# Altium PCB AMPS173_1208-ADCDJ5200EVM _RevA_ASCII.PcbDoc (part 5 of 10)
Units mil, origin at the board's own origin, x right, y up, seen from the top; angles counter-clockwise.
Board outline 10500 x 2750 mil, 14 copper layers (Top Copper, Layer 2 (GND1), Layer 3 (SIG1), Layer 4 (GND2, Layer 5 (PWR1), Layer 6 (GND3), Layer 7 (PWR/SIGNAL2), Layer 8 (PWR/SIGNAL3), Layer 9 (GND4), Layer 10 PWR2), Layer 11 (GND5), Layer 12 (SIG4), Layer 13 (GND6), Bottom Copper), stack 60.6 mil thick; 701 components, 826 nets, 3386 pads, 2128 vias.
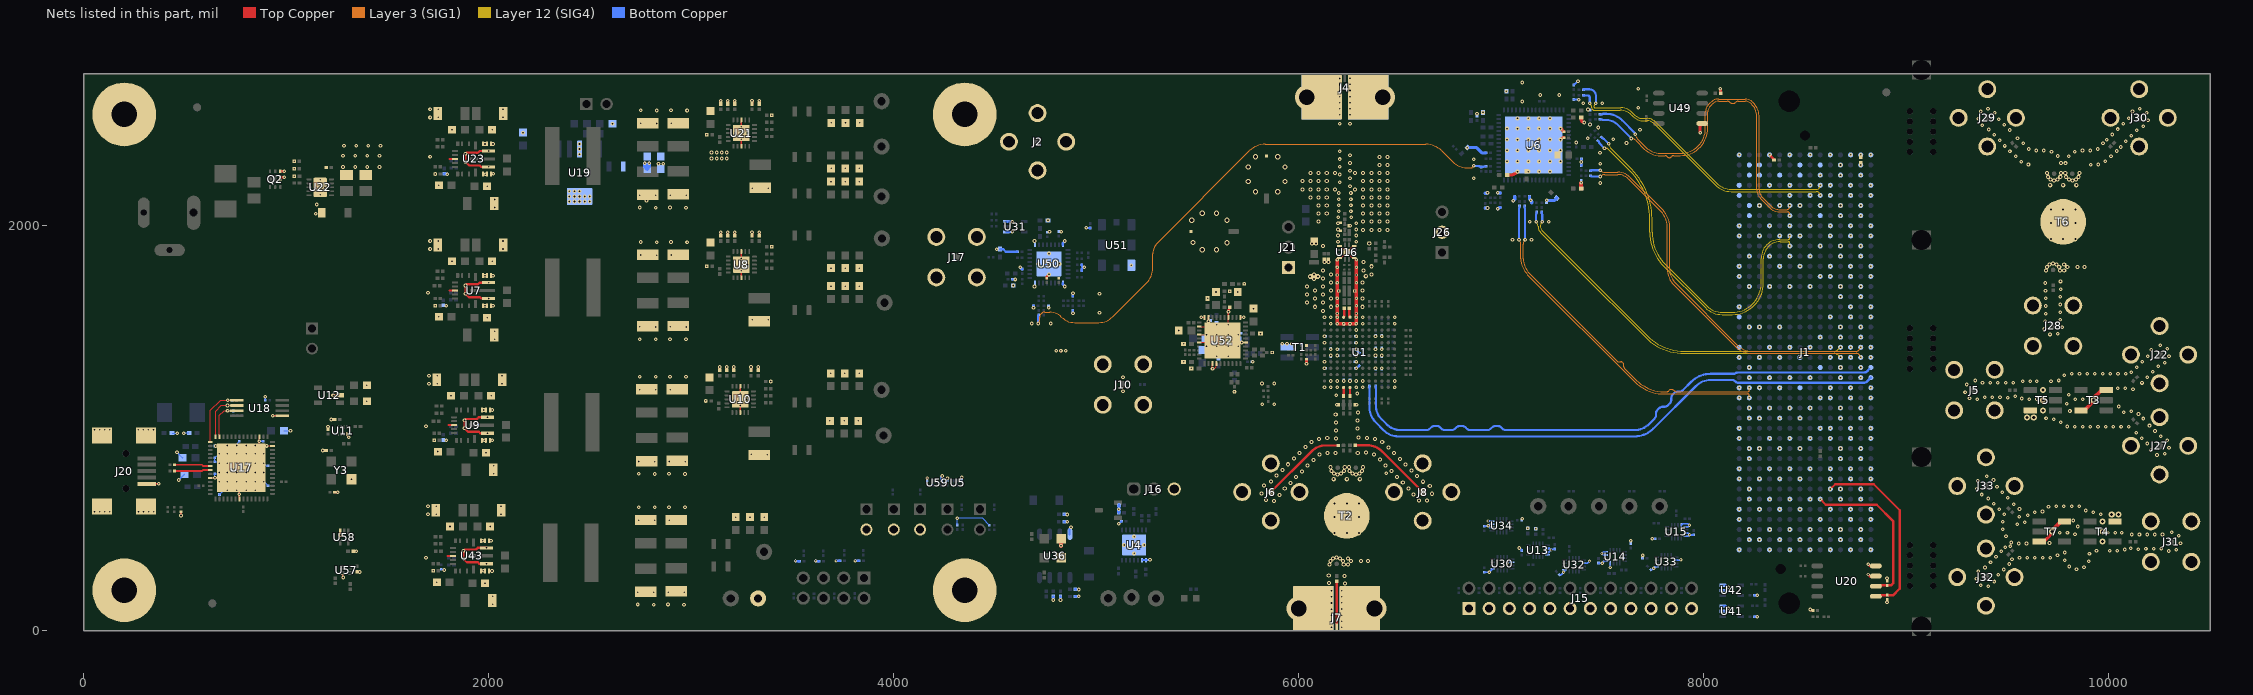
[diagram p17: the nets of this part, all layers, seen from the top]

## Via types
v1: diameter 18, hole 8, Top Copper to Bottom Copper, tented both sides, 1234 vias
v2: diameter 18, hole 8, Top Copper to Bottom Copper, tented top, 219 vias
v3: diameter 16, hole 8, Top Copper to Bottom Copper, tented both sides, 138 vias
v4: diameter 19.68, hole 7.87, Top Copper to Bottom Copper, 103 vias
v5: diameter 20, hole 10, Top Copper to Bottom Copper, tented top, 96 vias
v6: diameter 20, hole 10, Top Copper to Bottom Copper, tented both sides, 71 vias
v7: diameter 15.75/18/18/18/16/18/18/18/18/16/18/18/18/18 (per signal layer), hole 8, Top Copper to Bottom Copper, 50 vias
v8: diameter 20, hole 10, Top Copper to Bottom Copper, 40 vias
v9: diameter 15.75, hole 7.87, Top Copper to Bottom Copper, 28 vias
v10: diameter 21.81, hole 10, Top Copper to Bottom Copper, 26 vias
v11: diameter 15.75/16/16/16/16/16/16/16/16/16/16/16/16/18 (per signal layer), hole 8, Top Copper to Bottom Copper, 26 vias
v12: diameter 18, hole 8, Top Copper to Bottom Copper, tented bottom, 18 vias
v13: diameter 25.75, hole 15.75, Top Copper to Bottom Copper, 16 vias
v14: diameter 15.75/16/16/16/16/16/16/18/16/16/16/16/16/18 (per signal layer), hole 8, Top Copper to Bottom Copper, 15 vias
v15: diameter 30, hole 15, Top Copper to Bottom Copper, tented both sides, 12 vias
v16: diameter 15.75/16/16/16/18/16/16/16/16/16/16/16/16/18 (per signal layer), hole 8, Top Copper to Bottom Copper, 11 vias
v17: diameter 15.75/16/16/16/16/16/16/16/16/18/16/16/16/18 (per signal layer), hole 8, Top Copper to Bottom Copper, 7 vias
v18: diameter 15.75/16/16/16/16/16/16/18/16/18/16/16/16/18 (per signal layer), hole 8, Top Copper to Bottom Copper, 5 vias
v19: diameter 119.29, hole 77.95, Top Copper to Bottom Copper, 4 vias
v20: diameter 18, hole 8, Top Copper to Bottom Copper, 4 vias
v21: diameter 15.75/16/16/16/18/16/16/18/16/16/16/16/16/18 (per signal layer), hole 8, Top Copper to Bottom Copper, 2 vias
v22: diameter 15.75/16/16/16/16/16/18/16/16/16/16/16/16/18 (per signal layer), hole 8, Top Copper to Bottom Copper, 2 vias
v23: diameter 15.75/16/16/16/16/16/18/18/16/16/16/16/16/18 (per signal layer), hole 8, Top Copper to Bottom Copper, 1 vias

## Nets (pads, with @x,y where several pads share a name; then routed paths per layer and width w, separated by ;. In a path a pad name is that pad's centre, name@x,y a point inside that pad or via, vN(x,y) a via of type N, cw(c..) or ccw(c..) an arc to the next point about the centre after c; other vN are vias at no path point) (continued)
DB7_FMC_N: C44.1 J1.Y22 | length 2774.6
  Bottom Copper w10.5: C44.1@6381.14,1208.98 ccw(c6382.69,1207.43) 6381,1208.82 ccw(c6382.69,1207.43) 6380.5,1207.43 6380.5,1113.13 ccw(c6477.94,1113.13) 6409.04,1044.23 6433.65,1019.62 ccw(c6502.74,1088.71) 6502.74,991 6630,991 ; 7895.96,1186.96 7939.63,1230.63 cw(c8032.26,1138) 8032.26,1269 8148.99,1269 ccw(c8148.99,1279.69) 8156.55,1272.13 ; 7896,1187 cw(c7882.34,1200.66) 7882.34,1181.34 7873.36,1181.34 ccw(c7873.37,1154.03) 7854.06,1173.34 7845.8,1165.08 ccw(c7861.16,1149.72) 7839.43,1149.72 7839.43,1140.43 cw(c7815.29,1140.43) 7832.36,1123.36 7821,1112 cw(c7807.34,1125.66) 7807.34,1106.34 7798.36,1106.34 ccw(c7798.37,1079.03) 7779.06,1098.34 7770.8,1090.08 ccw(c7786.16,1074.72) 7764.43,1074.72 7764.43,1065.43 cw(c7740.29,1065.43) 7757.4,1048.4 cw(c7740.29,1065.43) 7757.36,1048.36 7729.29,1020.29 cw(c7658.58,1091) 7658.58,991 7021,991 ; 6630,991 ccw(c6630,1015.14) 6630.07,991 ; 6630,991 6630.07,991 ; 6630.07,991 ccw(c6630,1015.14) 6647.07,998.07 6653.64,1004.64 cw(c6669,989.27) 6669,1011 6680.69,1011 cw(c6680.69,983.69) 6699.99,1003.01 6706.34,996.66 ccw(c6720,1010.31) 6720,991 6755,991 ccw(c6755,1015.14) 6772.07,998.07 6778.64,1004.64 cw(c6794,989.27) 6794,1011 6805.69,1011 cw(c6805.69,983.69) 6824.99,1003.01 6831.34,996.66 ccw(c6845,1010.31) 6845,991 6931,991 ccw(c6931,1015.14) 6948.07,998.07 6954.64,1004.64 cw(c6970,989.27) 6970,1011 6981.69,1011 cw(c6981.69,983.69) 7000.99,1003.01 7007.34,996.66 ccw(c7021,1010.31) 7020.94,991 ; 7020.94,991 ccw(c7021,1010.31) 7021,991 ; 7020.94,991 7021,991
  Bottom Copper w11.5: 8156.55,1272.13 cw(c8167.9,1251.1) 8167.9,1275 8791.46,1275 ccw(c8791.46,1295.57) 8805.99,1281.01 J1.Y22@8817.32,1292.33
DB7_FMC_P: C43.1 J1.Y23 | length 2775.5
  Bottom Copper w10.5: C43.1@6348.85,1208.98 cw(c6347.28,1207.41) 6349,1208.81 cw(c6347.28,1207.41) 6349.5,1207.41 6349.5,1100.29 ccw(c6446.94,1100.29) 6378.04,1031.39 6420.14,989.29 ccw(c6490.85,1060) 6490.85,960 7658.58,960 ccw(c7658.58,1091) 7751.21,998.37 7961.55,1208.71 cw(c8032.26,1138) 8032.26,1238 8142,1238 cw(c8142,1223.17) 8152.48,1233.66 8152.96,1233.18
  Bottom Copper w11.5: 8152.96,1233.18 ccw(c8172.72,1252.94) 8172.72,1225 8788.45,1225 ccw(c8788.45,1252.9) 8808.17,1233.17 J1.Y23@8825,1250
EECLK: R168.1 U17.56 U18.2 | length 267.8
  Top Copper w5: U17.56@650.41,958.04 650.41,1083.41 679.59,1112.59 v1(709.41,1112.59) U18.2@756,1112.59
  Bottom Copper w5: v1(709.41,1112.59) 709.82,1113 R168.1@733.98,1113
EECS: R167.1 U17.1 U18.1 | length 330.2
  Top Copper w5: U17.1@624.82,932.45 624.82,1087.82 675.18,1138.18 v1(710.18,1138.18) U18.1@756,1138.18
  Bottom Copper w5: v1(710.18,1138.18) R167.1@732.98,1138.18
EEDATA: R170.2 U17.55 U18.3 | length 228.3
  Top Copper w5: U17.55@670.09,958.04 670.09,1063.09 694,1087 v1(710,1087) U18.3@756,1087
  Bottom Copper w5: v1(710,1087) 710.98,1086.02 R170.2@737,1086.02
FE_VDD: C113.1 C114.1 FB1.1 FB4.2
  other v1: 3100,2331.93 3125,2331.93 3150,2331.93 3175,2331.93 3100,2361.93 3125,2361.93 3150,2361.93 3175,2361.93
  other v5: 6076,1737 6056,1749 6096,1749 6076,1759
FGPA_GBTCLK5_FMC_N: J1.Z21 R44.2 | length 1871.4
  Layer 3 (SIG1) w3.25: v1(7489.42,2243.46) cw(c7512.06,2220.82) 7512.06,2252.83 7576,2252.83 cw(c7576,2180) 7627.5,2231.5 7790.71,2068.29 cw(c7720,1997.58) 7820,1997.58 7820,1786.17 ccw(c7931.25,1786.17) 7852.58,1707.51 8157.76,1402.33 ccw(c8236.42,1481) 8236.42,1369.75 8752.87,1369.75 cw(c8752.87,1350.12) 8766.73,1364.02 8770.93,1359.82 cw(c8761.12,1350) v2(8775,1350)
  Bottom Copper w10.5: R44.2@7441.02,2246.02 ccw(c7448.27,2253.27) 7448.27,2243.02 7488.38,2243.02 ccw(c7488.38,2244.5) v1(7489.42,2243.46)
FGPA_GBTCLK5_FMC_P: J1.Z20 R42.2 | length 1871
  Layer 3 (SIG1) w3.25: v1(7489.42,2273.46) ccw(c7512.06,2296.09) 7512.06,2264.08 7576,2264.08 cw(c7576,2180) 7635.46,2239.45 7798.67,2076.24 cw(c7720,1997.58) 7831.25,1997.58 7831.25,1786.17 ccw(c7931.25,1786.17) 7860.54,1715.46 8165.71,1410.29 ccw(c8236.42,1481) 8236.42,1381 8755,1381 ccw(c8755,1395.49) 8765.23,1385.23 8771.46,1391.46 ccw(c8762.93,1400) v2(8775,1400)
  Bottom Copper w10.5: R42.2@7441.02,2271.02 cw(c7448.27,2263.78) 7448.27,2274.02 7456.36,2274.02 7488.06,2274.02 cw(c7488.06,2272.09) v1(7489.42,2273.46)
FPGA_CLKA_FMC_N: J1.L25 R63.2 | length 1698.6
  Layer 3 (SIG1) w3.25: v1(7087.43,1931.41) cw(c7064.8,1908.78) 7096.81,1908.78 7096.81,1837.36 ccw(c7208.06,1837.36) 7129.39,1758.7 7658.95,1229.14 ccw(c7802.95,1373.13) 7802.95,1169.49 8217.66,1169.49 cw(c8217.66,1162.29) 8222.75,1167.38 cw(c8217.32,1161.95) 8225,1161.95 v2(8225,1150)
  Bottom Copper w10.5: v1(7087.43,1931.41) cw(c7088.48,1932.46) 7087,1932.46 7087,2082.62 cw(c7097.24,2082.62) 7090,2089.86 R63.2@7090,2097.95
FPGA_CLKA_FMC_P: J1.L24 R62.2 | length 1696.3
  Layer 3 (SIG1) w3.25: v1(7117.43,1931.41) ccw(c7140.07,1908.78) 7108.06,1908.78 7108.06,1837.36 ccw(c7208.06,1837.36) 7137.35,1766.65 7572.08,1331.92 ccw(c7581.62,1341.46) 7581.62,1327.97 7590.34,1327.97 cw(c7590.34,1315.75) 7598.98,1324.39 7603.42,1319.95 cw(c7598.06,1314.6) 7605.63,1314.6 7605.63,1303.01 ccw(c7616.83,1303.01) 7608.9,1295.1 7666.91,1237.09 ccw(c7802.95,1373.13) 7802.95,1180.74 7818.23,1180.74 ccw(c7818.23,1191.61) 7825.91,1183.92 7828.6,1186.61 cw(c7839.17,1176.05) 7839.17,1190.99 7840.42,1190.99 cw(c7840.42,1170.13) 7855.17,1184.88 7856,1184.06 ccw(c7864,1192.06) 7864,1180.74 8217.73,1180.74 ccw(c8217.73,1188.29) 8223.07,1182.95 ccw(c8218.41,1187.61) 8225,1187.61 v2(8225,1200)
  Bottom Copper w10.5: R62.2@7115,2097.95 7115,2089.86 cw(c7107.76,2082.62) 7118,2082.62 7118,1932.78 cw(c7116.06,1932.78) v1(7117.43,1931.41)
FPGA_CLKB_FMC_N: J1.G7 R40.2 | length 1676.1
  Layer 3 (SIG1) w3.25: v1(7641.16,2431.16) cw(c7641.16,2399.15) 7663.79,2421.78 7706.53,2379.04 ccw(c7785.2,2457.71) 7785.2,2346.46 7810,2346.46 cw(c7810,2335.5) 7817.75,2343.25 7821.88,2339.12 ccw(c7827,2344.24) 7827,2337 7832,2337 ccw(c7832,2346.66) 7838.83,2339.83 7840.84,2341.84 cw(c7852,2330.67) 7852,2346.46 7884.68,2346.46 ccw(c7884.68,2481.47) 8019.69,2481.47 8019.69,2563.24 cw(c8058,2563.24) 8030.91,2590.33 8041,2600.42 cw(c8075.06,2566.36) 8075.06,2614.53 8117,2614.53 cw(c8117,2598.91) 8128.05,2609.96 ccw(c8140,2621.9) 8140,2605 8148,2605 ccw(c8148,2617.07) 8156.54,2608.54 8157.96,2609.96 cw(c8169,2598.91) 8169,2614.53 8206,2614.53 cw(c8206,2579.5) 8230.77,2604.27 8240.39,2594.65 cw(c8188.32,2542.59) 8261.95,2542.59 8261.95,2179.22 ccw(c8326.8,2179.22) 8280.95,2133.37 8327.45,2086.86 ccw(c8371.16,2130.56) 8364.54,2069.11 ccw(c8371.16,2130.56) 8371.16,2068.75 8413.81,2068.75 cw(c8413.81,2057.56) 8425,2057.56 v2(8425,2050)
  Bottom Copper w10.5: R40.2@7487.05,2525 7495.14,2525 cw(c7495.14,2514.76) 7502.38,2522 7520,2522 cw(c7520,2444.75) 7574.63,2499.37 v1@7639.97,2434.03 ; v1@7639.98,2434.02 cw(c7637.1,2431.16) v1(7641.16,2431.16)
FPGA_CLKB_FMC_P: J1.G6 R37.2 | length 1680.2
  Layer 3 (SIG1) w3.25: v1(7662.37,2452.37) ccw(c7694.38,2452.37) 7671.75,2429.74 7714.49,2387 ccw(c7785.2,2457.71) 7785.2,2357.71 7884.68,2357.71 ccw(c7884.68,2481.47) 8008.44,2481.47 8008.44,2563.24 cw(c8058,2563.24) 8022.96,2598.29 8033.05,2608.38 ; 8033.05,2608.37 cw(c8075.06,2566.36) 8075.06,2625.78 8206,2625.78 cw(c8206,2579.5) 8238.72,2612.22 8248.34,2602.61 cw(c8188.32,2542.59) 8273.2,2542.59 8273.2,2179.22 ccw(c8326.8,2179.22) 8288.9,2141.32 8335.41,2094.81 ccw(c8371.16,2130.56) 8354.03,2082.99 ccw(c8371.16,2130.56) 8371.16,2080 8410,2080 ccw(c8410,2095) 8425,2095 v2(8425,2100)
  Bottom Copper w10.5: R37.2@7487.05,2550 7495.14,2550 ccw(c7495.14,2560.24) 7502.38,2553 7520,2553 cw(c7520,2444.75) 7596.55,2521.29 7660.18,2457.66 cw(c7654.9,2452.37) v1(7662.37,2452.37)
FPGA_GBTCLK0_FMC_N: J1.D5 R227.2 | length 1385.7
  Layer 12 (SIG4) w3.25: v1@7441.2,2600.45 cw(c7428.74,2588) 7446.35,2588 7446.35,2583.34 ccw(c7458.81,2583.34) 7458.81,2570.88 7586.41,2570.88 cw(c7586.41,2491.91) 7642.25,2547.75 7652.05,2537.95 ccw(c7698.41,2584.32) 7698.41,2518.75 7720,2518.75 cw(c7720,2472.06) 7753,2505.09 ; 7753.02,2505.07 7980.05,2278.05 8056.76,2201.33 ccw(c8135.42,2280) 8135.42,2168.75 8556.25,2168.75 cw(c8556.25,2150) v2(8575,2150)
  Bottom Copper w10.5: R227.2@7405.21,2644.98 ccw(c7407.21,2644.98) 7407.21,2642.98 7427.64,2642.98 cw(c7427.64,2633.86) 7436.76,2633.86 7436.76,2604.89 v1(7436.98,2604.67)
FPGA_GBTCLK0_FMC_P: J1.D4 R226.2 | length 1419
  Layer 12 (SIG4) w3.25: v1@7462.76,2600.45 ccw(c7475.22,2588) 7457.61,2588 ccw(c7463.48,2588) 7463.48,2582.13 7591.07,2582.13 cw(c7591.07,2503.16) 7646.89,2559.02 7660,2545.91 ; 7660.03,2545.88 ccw(c7698.41,2584.32) 7698.41,2530 7720,2530 cw(c7720,2472.06) 7760.97,2513.03 7988,2286 8064.71,2209.29 ccw(c8135.42,2280) 8135.42,2180 8555,2180 ccw(c8555,2200) v2(8575,2200)
  Bottom Copper w10.5: R226.2@7405.21,2671.98 cw(c7407.21,2671.98) 7407.21,2673.98 7435.53,2673.98 cw(c7435.53,2642.98) 7457.45,2664.9 cw(c7432.56,2640.01) 7467.76,2640.01 7467.76,2606.55 cw(c7465.1,2606.55) v1(7466.98,2604.67)
FPGA_GBTCLK1_FMC_N: J1.B21 R41.2 | length 1831.4
  Layer 12 (SIG4) w3.25: v1(7172.03,2019.51) 7172.82,2018.72 cw(c7152.11,1998) 7181.4,1998 ccw(c7225.61,1998) 7194.34,1966.75 7369.91,1791.18 7712.33,1448.76 ccw(c7903.08,1639.51) 7903.08,1369.75 8643.34,1369.75 cw(c8643.34,1341) 8663.67,1361.33 v2(8675,1350)
  Bottom Copper w10.5: v1(7172.03,2019.51) cw(c7173.07,2020.56) 7171.59,2020.56 7171.59,2052.57 cw(c7181.84,2052.57) 7174.59,2059.82 R41.2@7174.59,2067.91
FPGA_GBTCLK1_FMC_P: J1.B20 R38.2 | length 1813.9
  Layer 12 (SIG4) w3.25: v1(7202.03,2019.51) 7201.23,2018.72 ccw(c7221.95,1998) 7192.65,1998 ccw(c7225.61,1998) 7202.31,1974.69 7720.29,1456.71 ccw(c7903.08,1639.5) 7903.08,1381 8648,1381 ccw(c8648,1400.31) 8661.66,1386.66 v2(8675,1400)
  Bottom Copper w10.5: R38.2@7199.59,2067.91 7199.59,2059.82 cw(c7192.35,2052.57) 7202.59,2052.57 7202.59,2020.88 cw(c7200.66,2020.88) v1(7202.03,2019.51)
FPGA_SYSREF_FMC_N: J1.G10 R53.2 | length 1726.2
  Layer 12 (SIG4) w3.25: v1(7509.84,2383) 7519.7,2383 cw(c7519.7,2374.81) 7525.49,2380.6 7635.36,2270.74 cw(c7398.5,2033.88) 7733.47,2033.88 7733.47,1967.2 ccw(c7968.23,1967.2) 7802.23,1801.2 8006.72,1596.71 ccw(c8091.79,1681.78) 8091.79,1561.47 8141.2,1561.47 ccw(c8141.2,1714.65) 8294.38,1714.65 8294.38,1838.21 cw(c8376.92,1838.21) 8376.92,1920.75 8417.51,1920.75 cw(c8417.51,1913.26) 8425,1913.26 v2@8425,1901.5
  Bottom Copper w10.5: R53.2@7477.43,2419.04 7483.15,2413.32 ccw(c7493.39,2413.32) 7486.15,2406.08 7508.79,2383.44 ccw(c7509.84,2384.48) v1(7509.84,2383)
  other v2: 8425,1900
FPGA_SYSREF_FMC_P: J1.G9 R51.2 | length 1715.1
  Layer 12 (SIG4) w3.25: v1(7531.05,2404.22) ccw(c7563.06,2404.22) 7540.42,2381.58 7643.32,2278.69 cw(c7398.51,2033.88) 7744.72,2033.88 7744.72,1967.2 ccw(c7968.22,1967.2) 7810.18,1809.16 8014.68,1604.66 ccw(c8091.79,1681.78) 8091.79,1572.72 8141.2,1572.72 ccw(c8141.2,1714.65) 8283.13,1714.65 8283.13,1840.04 cw(c8375.09,1840.04) 8375.09,1932 8415.67,1932 ccw(c8415.67,1941.33) 8425,1941.33 v2(8425,1950)
  Bottom Copper w10.5: R51.2@7495.1,2436.72 7500.83,2431 cw(c7500.83,2420.75) 7508.06,2428 7530.48,2405.59 cw(c7529.11,2404.22) v1(7531.05,2404.22)
FTDI_D_N: R156.2 U17.7 | length 180.1
  Top Copper w9.5: R156.2@447.05,820 583.5,820 589.16,814.34 U17.7@624.82,814.34
FTDI_D_P: R157.2 U17.8 | length 180.1
  Top Copper w9.5: 583.5,789 589.16,794.66 U17.8@624.82,794.66
  Top Copper w10: R157.2@447.02,789 583.5,789
GA0_FMC: J1.C34 R218.1 U20.1 | length 927.4
  Top Copper w11.5: v2(8625,700) 8649,724 8839,724 8968,595 8968,208 8934.81,174.81 8854.5,174.81 U20.1@8849.68,170
GA1_FMC: J1.D35 R220.1 U20.2 | length 803.3
  Top Copper w11.5: v2(8575,650) 8602.25,622.75 8854.25,622.75 8935,542 8935,235 8923.98,223.98 R220.1@8905,223.98 8853.66,223.98 U20.2@8849.68,220
GND: C6.2 C7.2 C8.2 C9.2 C10.2 C11.2 C12.2 C47.2 C48.2 C51.2 C53.1 C54.1 C55.1 C56.1 C57.1 C58.2 C59.2 C62.2 C63.2 C64.2 C65.2 C66.2 C68.2 C69.2 C70.2 C71.2 C72.2 C76.1 C77.1 C78.1 C79.1 C80.2 C81.1 C82.1 C83.2 C84.1 C85.2 C86.1 C87.2 C88.2 C89.1 C92.2 C94.2 C95.2 C96.2 C97.2 C100.2 C101.2 C102.2 C103.2 C104.2 C106.1 C109.2 C110.2 C111.2 C112.2 C113.2 C114.2 C115.1 C116.1 C118.1 C124.1 C125.1 C126.2 C128.2 C130.2 C131.2 C132.2 C133.2 C134.2 C135.2 C136.1 C137.1 C139.2 C140.2 C141.2 C142.2 C144.2 C145.2 C146.2 C147.2 C156.1 C157.1 C158.1 C159.1 C160.1 C161.1 C162.1 C163.1 C167.1 C168.1 C169.1 C170.1 C171.1 C172.1 C173.1 C174.1 C175.1 C176.1 C178.1 C179.1 C180.1 C181.1 C182.1 C183.1 C184.2 C185.2 C186.2 C187.2 C188.2 C189.2 C190.2 C192.1 C193.1 C195.2 C199.2 C201.2 C202.2 C203.2 C204.1 C205.2 C206.2 C207.1 C209.2 C210.2 C211.2 C212.2 C213.2 C214.2 C215.2 C216.2 C217.2 C218.2 C220.1 C221.1 C223.2 C224.2 C225.2 C226.2 C227.2 C229.2 C230.2 C231.2 C236.2 C237.2 C241.2 C242.2 C243.2 C244.2 C245.2 C287.1 C288.1 C290.2 C307.2 C308.2 C309.2 C310.2 C311.2 C312.2 C313.2 C314.2 C315.2 C316.2 C317.2 C318.2 C320.2 C323.2 C324.2 C325.2 C326.2 C327.1 C328.1 C329.1 C330.1 C331.2 C332.2 C333.2 C334.2 C335.2 C336.2 C338.2 C339.1 C340.1 C341.1 C342.1 C343.1 C344.1 C345.1 C359.1 C360.1 C405.1 C415.2 C416.2 C417.2 C421.2 C422.2 C423.2 C424.2 C425.2 C426.2 C427.2 C428.2 C429.2 C430.2 C431.2 C432.2 C433.2 D2.2 D3.2 D6.2 H1.1 H2.1 H3.1 H4.1 J1.A1 J1.A4 J1.A5 J1.A8 J1.A9 J1.A12 J1.A13 J1.A16 J1.A17 J1.A20 J1.A21 J1.A24 J1.A25 J1.A28 J1.A29 J1.A32 J1.A33 J1.A36 J1.A37 J1.A40 J1.B2 J1.B3 J1.B6 J1.B7 J1.B10 J1.B11 J1.B14 J1.B15 J1.B18 J1.B19 J1.B22 J1.B23 J1.B26 J1.B27 J1.B30 J1.B31 J1.B34 J1.B35 J1.B38 J1.B39 J1.C1 J1.C4 J1.C5 J1.C8 J1.C9 J1.C12 J1.C13 J1.C17 J1.C20 J1.C21 J1.C24 J1.C25 J1.C28 J1.C29 J1.C32 J1.C33 J1.C36 J1.C38 J1.C40 J1.D2 J1.D3 J1.D6 J1.D7 J1.D10 J1.D13 J1.D19 J1.D22 J1.D25 J1.D28 J1.D37 J1.D39 J1.E1 J1.E4 J1.E5 J1.E8 J1.E11 J1.E14 J1.E20 J1.E23 J1.E26 J1.E29 J1.E32 J1.E35 J1.E38 J1.E40 J1.F2 J1.F3 J1.F6 J1.F9 J1.F12 J1.F21 J1.F24 J1.F27 J1.F30 J1.F33 J1.F36 J1.F39 J1.G1 J1.G4 J1.G5 J1.G8 J1.G11 J1.G14 J1.G20 J1.G23 J1.G26 J1.G29 J1.G32 J1.G35 J1.G38 J1.G40 J1.H3 J1.H6 J1.H9 J1.H12 J1.H18 J1.H21 J1.H24 J1.H27 J1.H30 J1.H33 J1.H36 J1.H39 J1.J1 J1.J4 J1.J8 J1.J11 J1.J14 J1.J20 J1.J23 J1.J26 J1.J29 J1.J32 J1.J35 J1.J38 J1.J40 J1.K2 J1.K3 J1.K6 J1.K9 J1.K18 J1.K21 J1.K24 J1.K27 J1.K30 J1.K33 J1.K36 J1.K39 J1.L2 J1.L3 J1.L6 J1.L7 J1.L11 J1.L14 J1.L18 J1.L22 J1.L23 J1.L26 J1.L27 J1.L30 J1.L31 J1.L34 J1.L35 J1.L38 J1.L39 J1.M1 J1.M4 J1.M5 J1.M8 J1.M9 J1.M12 J1.M13 J1.M16 J1.M17 J1.M20 J1.M21 J1.M24 J1.M25 J1.M28 J1.M29 J1.M32 J1.M33 J1.M36 J1.M37 J1.M40 J1.Y1 J1.Y4 J1.Y5 J1.Y8 J1.Y9 J1.Y12 J1.Y13 J1.Y16 J1.Y17 J1.Y20 J1.Y21 J1.Y24 J1.Y25 J1.Y28 J1.Y29 J1.Y32 J1.Y33 J1.Y36 J1.Y37 J1.Y40 J1.Z2 J1.Z3 J1.Z6 J1.Z7 J1.Z10 J1.Z11 J1.Z14 J1.Z15 J1.Z18 J1.Z19 J1.Z22 J1.Z23 J1.Z26 J1.Z27 J1.Z30 J1.Z31 J1.Z34 J1.Z35 J1.Z38 J1.Z39 J2.2 J2.3 J2.4 J2.5 J4.2 J4.3 J6.2 J6.3 J6.4 J6.5 J7.2 J7.3 J8.2 J8.3 J8.4 J8.5 J9.2 J10.2 J10.3 J10.4 J10.5 J11.2 J13.2 J15.1 J15.3 J15.5 J15.7 J15.9 J15.11 J15.13 J15.15 J15.17 J15.19 J15.21 J15.23 J16.3 J17.2 J17.3 J17.4 J17.5 J20.5 J20.6 J20.7 J20.8 J20.9 J21.1 J24.2 J25.2 J26.2 Q2.4 Q2.7 R1.1 R2.1 R7.1 R12.1 R13.2 R28.1 R30.1 R31.2 R43.2 R45.1 R46.1 R47.1 R48.1 R50.1 R52.1 R55.1 R56.1 R57.1 R58.1 R64.1 R65.1 R69.1 R73.1 R74.1 R84.1 R89.1 R97.1 R100.1 R101.1 R102.1 R104.2 R107.2 R108.1 R110.1 R111.1 R112.1 R120.1 R121.1 R122.1 R123.1 R124.1 R125.1 R126.1 R137.1 R138.1 R139.1 R140.1 R141.1 R142.1 R143.1 R145.1 R146.2 R147.1 R160.1 R164.1 R166.2 R175.1 R176.1 R184.1 R189.1 R193.1 R199.1 R216.1 R218.2 R220.2 R232.1 R238.1 R243.1 R244.1 R248.1 R249.1 R250.1 R256.1 R264.1 R359.1 R360.1 R750.1 R801.1 T1.2 T2.4 TP6.1 U1.A1 U1.A2 U1.A3 U1.A6 U1.A7 U1.A12 U1.B2 U1.B3 U1.B4 U1.B5 U1.B6 U1.B7 U1.B12 U1.C6 U1.D1 U1.D6 U1.D9 U1.D10 U1.E1 U1.E6 U1.F2 U1.F3 U1.F6 U1.F9 U1.F10 U1.G2 U1.G3 U1.G6 U1.G9 U1.G10 U1.H1 U1.H6 U1.J1 U1.J6 U1.J9 U1.J10 U1.L2 U1.L3 U1.L4 U1.L5 U1.L6 U1.L7 U1.L12 U1.M1 U1.M2 U1.M3 U1.M6 U1.M7 U1.M12 U4.8 U4.9 U4.15 U5.3 U6.65 U7.5 U7.6 U7.7 U7.8 U7.10 U7.11 U7.12 U7.13 U7.20 U8.8 U8.18 U8.21 U9.5 U9.6 U9.7 U9.8 U9.10 U9.11 U9.12 U9.13 U9.20 U10.8 U10.18 U10.21 U11.4 U12.2 U13.6 U13.7 U13.8 U14.4 U14.5 U14.7 U14.8 U15.4 U15.5 U15.7 U15.8 U16.1 U16.4 U16.7 U16.10 U16.13 U17.10 U17.21 U17.41 U17.45 U17.57 U18.5 U19.3 U19.6 U20.3 U20.4 U21.8 U21.18 U21.21 U22.11 U23.5 U23.6 U23.7 U23.8 U23.10 U23.11 U23.12 U23.13 U23.20 U30.6 U30.13 U31.1 U31.3 U32.6 U32.13 U33.6 U33.13 U34.6 U34.7 U34.8 U36.4 U41.2 U41.3 U42.2 U42.3 U43.5 U43.6 U43.7 U43.8 U43.10 U43.11 U43.12 U43.13 U43.20 U49.5 U50.1 U50.8 U50.17 U50.24 U50.33 U51.3 U52.2 U52.4 U52.6 U52.13 U52.14 U52.25 U52.31 U52.34 U52.39 U52.40 U52.41@5623.03,1433.38 U57.4 U58.3 U59.3 Y3.2 | length 7588
  Top Copper w5: U16.10@6200.66,1840.56 6207.55,1840.56 v4(6237.08,1870.09) ; U16.7@6200.66,1899.62 6207.55,1899.62 v4(6237.08,1870.09) ; U16.1@6273.49,1840.56 6266.6,1840.56 v4(6237.08,1870.09) ; U16.4@6273.49,1899.62 6266.6,1899.62 v4(6237.08,1870.09)
  Top Copper w6: U17.10@624.82,755.29 v1(647.71,755.29) 729.15,755.29 v4(755.27,781.41) U17.57@768.52,794.66 ; U17.57@778.36,804.5 v4(801.45,827.59) U17.57@866.94,893.08 ; U17.45@866.94,958.04 v1(866.94,935.56) U17.57@866.94,893.08 ; U17.41@931.91,912.77 886.63,912.77 U17.57@866.94,893.08 ; U11.4@1298.8,971.15 1298.8,965.2 v1(1308,956) ; U52.6@5508.86,1423.54 5613.19,1423.54 U52.41@5623.03,1433.38 ; U52.4@5508.86,1462.91 U52.41@5593.5,1462.91 ; U52.2@5508.86,1502.28 U52.41@5554.13,1502.28 ; v1(5518.45,1547.55) U52.40@5534.45,1547.55 ; U52.39@5554.13,1547.55 U52.41@5554.13,1502.28 ; U52.13@5573.82,1319.2 5573.82,1294.18 v1(5574.21,1293.79) 5583.21,1293.79 5593.5,1304.09 U52.14@5593.5,1319.2 ; U52.34@5652.56,1547.55 5652.56,1462.91 v4(5651.77,1462.12) U52.41@5623.03,1433.38 ; U52.31@5711.61,1547.55 v1(5727.96,1547.55) ; U52.41@5554.13,1502.28 U52.41@5593.5,1462.91 ; U52.41@5593.5,1462.91 v4(5594.29,1462.12) U52.41@5623.03,1433.38
  Top Copper w7: v1@1278.28,263 U57.4@1278.28,277.33
  Top Copper w8: J20.5@310.47,725.81 v1(370.19,725.81) ; v1(480,569) R166.2@480,587.98 ; U17.21@768.52,650.96 v1(768.52,673.52) 768.52,794.66 U17.57@778.36,804.5 ; v1(933.59,1061.41) U18.5@980.41,1061.41 ; R175.1@1206,994.02 v1(1206,1006.62) ; U52.34@5652.56,1547.55 5652.56,1574.15 v1(5653.21,1574.79)
  Top Copper w9: v1(1221.47,1043) C207.1@1238.01,1043 ; v1@1278.28,263 v1(1281,263) ; U10.18@3242,1078.04 v4(3242,1112.49) U10.21@3242,1143 v4(3242,1173.51) U10.8@3242,1207.96 ; U8.18@3247,1743.04 v4(3247,1777.49) U8.21@3247,1808 v4(3247,1838.51) U8.8@3247,1872.96 ; U21.18@3247,2393.04 v4(3247,2427.49) U21.21@3247,2458 v4(3247,2488.51) U21.8@3247,2522.96
  Top Copper w9.8: 1795,370 U43.20@1823.46,370 ; 1800,1015 U9.20@1828.46,1015 ; 1805,1680 U7.20@1833.46,1680 ; 1805,2330 U23.20@1833.46,2330 ; v1@1881.06,401.06 v1(1875,395) v1(1875,355) 1892.21,337.79 ; v1@1886.06,1046.06 v1(1880,1040) v1(1880,1000) 1897.21,982.79 ; v1@1891.06,1711.06 v1(1885,1705) v1(1885,1665) 1902.21,1647.79 ; v1@1891.06,2361.06 v1(1885,2355) v1(1885,2315) 1902.21,2297.79
  Top Copper w10: v1(5653.21,1574.79) 5653.21,1585.79 5659.19,1591.78 C336.2@5659.19,1597.79
  Top Copper w11.5: Q2.7@970.59,2233.74 970.59,2240 v1(990,2240) ; Q2.4@970.59,2268.39 970.59,2270 v1(990,2270) ; v1(1179.47,890) C204.1@1196.01,890 ; v1(1231,1163) U12.2@1265.13,1163 ; R801.1@1237.91,684.44 1254.15,684.44 v1(1254.56,684.03) ; C359.1@1349,292.01 1349,290 v1(1362,290) ; v1@1881.06,401.06 1937.06,401.06 1945.37,409.37 v9(1988.82,409.37) ; v1@1886.06,1046.06 1942.06,1046.06 1950.37,1054.37 v9(1993.82,1054.37) ; v1@1891.06,1711.06 1947.06,1711.06 1955.37,1719.37 v9(1998.82,1719.37) ; v1@1891.06,2361.06 1947.06,2361.06 1955.37,2369.37 v9(1998.82,2369.37) ; 1892.21,337.79 1945.54,337.79 1952.7,330.63 v9(1988.82,330.63) ; 1897.21,982.79 1950.54,982.79 1957.7,975.63 v9(1993.82,975.63) ; 1902.21,1647.79 1955.54,1647.79 1962.7,1640.63 v9(1998.82,1640.63) ; 1902.21,2297.79 1955.54,2297.79 1962.7,2290.63 v9(1998.82,2290.63) ; C310.2@4755,1741.02 4755,1749.09 v4(4766.3,1760.39) ; v1@4821.4,1384 4824.4,1381 v1(4825.4,1382) ; v1@7394.69,2212.09 v1(7395,2212.4) ; v1(8082,2676) v1@8082.99,2675.01 ; v2(8325,2350) 8344.89,2330.11 cw(c8339.78,2325) R104.2@8347.01,2325 ; v3(8811.81,277.87) 8819.69,270 U20.3@8849.68,270 ; v3(8811.81,327.87) 8819.69,320 U20.4@8849.68,320
  Top Copper w12: v1(8525,105) 8530,100 C92.2@8538.98,100
  Top Copper w12.5: R120.1@3140,1285.98 v1(3140,1302.52) ; R100.1@3145,1950.98 v1(3145,1967.52) ; R137.1@3145,2600.98 v1(3145,2617.52) ; R122.1@3175,1285.98 v1(3175,1302.52) ; R101.1@3180,1950.98 v1(3180,1967.52) ; R139.1@3180,2600.98 v1(3180,2617.52) ; R123.1@3210,1285.98 v1(3210,1302.52) ; R102.1@3215,1950.98 v1(3215,1967.52) ; R140.1@3215,2600.98 v1(3215,2617.52) ; R124.1@3295,1285.98 v1(3295,1302.52) ; R110.1@3300,1950.98 v1(3300,1967.52) ; R141.1@3300,2600.98 v1(3300,2617.52) ; R125.1@3330,1285.98 v1(3330,1302.52) ; R111.1@3335,1950.98 v1(3335,1967.52) ; R142.1@3335,2600.98 v1(3335,2617.52)
  Top Copper w13: v2(6038,1318.95) R1.1@6038,1337.95
  Top Copper w15: C57.1@7394.69,2535 7394.69,2525.32 ccw(c7410,2525.32) v1(7410,2510)
  Top Copper w15.5: C47.2@7029.69,2250 7040.56,2250 ccw(c7040.56,2305.78) v4@7080,2266.34 ; v4@7292.2,2425 7302.2,2435 R31.2@7308.98,2435 ; v4@7292.2,2478.54 7295.43,2478.54 R43.2@7308.98,2465 ; v1(7982,2460) 7982,2494.72 U49.5@7992.28,2505 ; C51.2@8082.99,2655 v1@8082.99,2675.01
  Top Copper w18: v3(6189.76,1832.6) v3(6189.76,1794.6) v3(6189.76,1756.6) v3(6189.76,1718.6) v3(6189.76,1642.6) v3(6189.76,1604.6) v3(6189.76,1566.6) v7(6189.76,1548.23) v7(6189.76,1516.73) v7(6221.26,1516.73) v7(6252.76,1516.73) v7(6284.25,1516.73) U1.A6@6284.25,1548.23 6284.64,1548.62 v3(6284.64,1566.6) v3(6284.64,1604.6) v3(6284.64,1642.6) v3(6284.64,1718.6) v3(6284.64,1756.6) v3(6284.64,1794.6) v3(6284.64,1832.6)
  Top Copper w20: v1(4826,419) 4826,425.98 4826.34,426.32 D2.2@4826.34,455 ; C53.1@7394.69,2185 v1@7394.69,2212.09
  Bottom Copper w6: C88.2@435.69,976 v1(460.71,976) ; v1(493,976) 494,977 C87.2@520.31,977 ; C82.1@647.02,912.5 v20(651,912.5) ; v1(647.71,755.29) 647,756 C84.1@647,775 661.62,775 v4(668.03,781.41) ; v4(668.03,827.59) 661.62,834 R160.1@647.02,834 C86.1@647.02,853.5 647.76,853.5 v4(668.03,873.77) ; v4(755.27,914.83) 755.27,922.27 768.52,935.52 C79.1@768.52,936 ; v4(888.7,735.23) 890.55,735.23 C81.1@909.86,715.92 ; v4(888.7,827.59) 901.94,814.34 C76.1@909.86,814.34 ; C80.2@988,988.5 v1(1020.5,988.5) ; R232.1@1765,303.98 1776.02,303.98 v1(1780,300) ; R69.1@4313,522.05 v1(4313,556) 4314,557 4436.02,557 R28.1@4472,521.02 ; C326.2@5704.58,1437.16 C326.2@5704.58,1443.79 ; v3(7538,313) 7538.5,313.5 U14.4@7538.5,335
  Bottom Copper w8: v1(460,881) C85.2@487.5,853.5 ; v1(469,744.5) C83.2@497,772.5 ; C77.1@670.09,673 691.26,694.17 v4(709.09,694.17) ; v1(866.94,935.56) 867.39,936 C78.1@886.63,936 ; C89.1@896,1138 v1(896,1155) ; C433.2@6915,288.98 6939.98,288.98 v3(6940.38,289) U30.13@6957.76,306.38 ; C428.2@6915,516.02 6934.02,516.02 v3(6936,518) ; v3@6940,542 v3(6935,542) 6935.38,541.62 U34.8@6954.76,541.62 ; U34.6@6954.76,510.13 6943.87,510.13 v3(6936,518) ; U34.7@6954.76,525.87 6943.87,525.87 v3(6936,518) ; v3(7030.23,334.73) 7033.37,337.87 U30.6@7052.24,337.87 ; v1@7092.5,408.62 7100,401.12 C422.2@7100,396.02 ; C427.2@7101.02,545 7101.02,555.79 v1(7103.69,553.12) ; v3(7170.98,503.39) R74.1@7174.95,499.41 ; U13.8@7227.99,374.72 U13.7@7227.99,390.47 7237.47,390.47 v3(7246,399) ; U13.6@7227.99,406.22 7238.78,406.22 v3(7246,399) ; C421.2@7265,403.98 7265,402.25 7249.25,402.25 v3(7246,399) ; C430.2@7287.79,277.21 7296.46,277.21 v3(7307.83,288.58) 7312.76,293.5 U32.13@7312.76,301.38 ; U32.6@7407.24,332.87 7424.87,332.87 v3(7436,344) ; C423.2@7480,333.98 7498.02,333.98 v3(7499,333) 7508.87,342.87 U14.5@7514.88,342.87 ; U14.7@7514.88,374.37 7504.63,374.37 v3(7497,382) 7505.12,390.12 U14.8@7514.88,390.12 ; R750.1@7697.98,358 v1(7697.98,371.98) ; C429.2@7737.79,302.21 7746.21,302.21 v3(7753,309) 7760.38,316.38 U33.13@7767.76,316.38 ; v1(7745,455) C426.2@7758.98,455 ; U33.6@7862.24,347.87 7883.87,347.87 v3(7887,351) ; U15.4@7888.62,521.5 7896.13,529 7921,529 v3(7929,521) 7921.62,513.62 U15.5@7912.24,513.62 ; U15.8@7912.24,466.38 7922.38,466.38 v3(7930,474) 7921.87,482.13 U15.7@7912.24,482.13 ; U41.2@8093.71,96.73 8106.73,96.73 v3(8121,111) 8109.68,122.32 U41.3@8093.71,122.32 ; U42.2@8093.71,199.41 8106.41,199.41 v3(8122,215) 8112,225 U42.3@8093.71,225
  Bottom Copper w9: v1(5110.98,599.92) v1@5112.01,600.95 ; v1(5111.38,528.19) 5123.19,540 C417.2@5123.98,540 ; U4.9@5226.62,348.67 U4.8@5246.31,348.67 5263.67,348.67 v1(5265,350)
  Bottom Copper w10: v1@4883.98,1571.02 R243.1@4883.98,1581.48 R243.1@4883.98,1583.98 ; R244.1@4883.98,1651.02 R244.1@4883.98,1653.52 v1@4883.98,1663.98 ; C168.1@6279.02,1296 C168.1@6285,1296 ; C169.1@6279.02,1391 6297.23,1372.79 C125.1@6299.21,1372.79 ; C168.1@6286,1296 C168.1@6285,1296 ; C124.1@6298.21,1309.21 C168.1@6285,1296 ; R256.1@7358.19,2622.95 v1(7382,2623) ; R238.1@7358.19,2695 7374.2,2711.01 cw(c7379,2706.21) v1(7379,2713) ; R50.1@7395,2297.05 v1(7395,2315) 7396.02,2316.02 C65.2@7396.02,2330 ; v3(7930,474) C425.2@7950,473.98
  Bottom Copper w11.5: R138.1@1780,2257.01 1792.99,2257.01 v1(1795,2255) ; v3(3515,345) 3517.02,342.98 R147.1@3533.98,342.98 ; v3(3615,345) 3616.81,343.19 R108.1@3630.35,343.19 ; v3(3715,345) 3716.02,346.02 R89.1@3733.98,346.02 ; v3(3810,345) R84.1@3827.95,345 ; U59.3@4234.69,741.81 4234.69,759.68 v1(4239,764) ; U5.3@4334.69,741.81 4334.69,756.68 v1(4335,757) ; R248.1@4525,1884.68 4540.31,1884.68 4552.91,1872.09 C320.2@4611.06,1872.09 ; U31.1@4555.71,1969.41 v1@4584.41,1969.41 ; U31.3@4555.71,2020.59 v1@4584.41,2020.59 ; C96.2@4586.02,1735 v1(4600,1735) ; v1(4625,1795) ccw(c4633.98,1795) 4633.98,1786.02 C318.2@4635,1786.02 ; v1(4690,1595) 4690.45,1595.45 R249.1@4690.45,1606.02 ; v1(4788,152) C288.1@4787.99,169.57 ; v1(4823,152) R216.1@4822.99,169.57 ; U50.1@4835.2,1717.09 4835.2,1709.8 v1(4845,1700) ; U50.24@4835.2,1906.06 4835.2,1915.2 v1(4845,1925) ; R164.1@4841.17,539 v1(4856,539) ; C405.1@4842.02,574 v1(4857,574) ; U36.4@4867.99,476.85 4867.99,503.99 v1(4875,511) ; v1@4883.98,1571.02 v1@4885,1570 ; v1@4883.98,1663.98 v1@4885,1665 ; R176.1@4895.98,204.25 4896.24,204 v1(4914,204) ; C287.1@4896.73,170 v1(4914,170) ; C312.2@4928.11,1777.09 4928.11,1783.46 cw(c4939.92,1783.46) v1(4939.92,1795.28) cw(c4939.92,1807.09) C317.2@4928.11,1807.09 ; v1(4950,1990) 4951.02,1988.98 C323.2@4970,1988.98 ; C432.2@8251.02,70 v1(8263.62,70) ; C431.2@8251.02,175 v1(8263.62,175)
  Bottom Copper w12: v4(5701.77,1462.12) 5701.77,1446.61 5704.58,1443.79 C326.2@5706.52,1443.79
  Bottom Copper w15: C326.2@5704.58,1437.16 v1(5718.21,1423.54) ; v1(7059,2123) 7066.48,2130.48 R65.1@7066.48,2145 ; v1(7225,2125.75) 7263.58,2125.75 C54.1@7273.92,2136.08
  Bottom Copper w15.5: C415.2@5110.98,583.19 v1(5110.98,599.92) ; v1@5112.01,600.95 C416.2@5112.01,620 ; v1(6832.54,2385.73) 6878.27,2385.73 6904,2360 C6.2@6923.98,2360 ; R359.1@6920,2088.52 6930.79,2088.52 v1(6931.81,2087.5) ; R360.1@6920,2160.57 6929.88,2160.57 v1(6931.81,2162.5) ; v1(6981.92,2162.21) 6982.08,2162.05 R58.1@6995,2162.05 ; v1(6982.79,2084.36) 6983.78,2085.35 cw(c6995,2074.14) R57.1@6995,2090 ; R64.1@7138.52,2145 7138.52,2132.22 v1(7145,2125.75) 7150.38,2120.36 R48.1@7150.38,2113.93 ; v1(7382,2623) v1(7382,2623)
  Bottom Copper w18: C113.2@2781.68,2280.03 C113.2@2781.68,2297.27 ; C113.2@2781.68,2280.03 2770,2291.71 v1(2770,2308.95) C113.2@2781.68,2297.27 ; C113.2@2781.68,2280.03 2793,2291.35 v1(2793,2308.95) 2781.68,2297.64 C113.2@2781.68,2297.27
  other v1: 6161.46,17.04 6212.6,17.5 6161.46,47.04 6212.6,47.5 6161.46,77.04 6212.6,77.5 6161.46,107.04 6212.6,107.5 2814.15,129.13 2964.15,129.13 2020,130 2735,130 2885,130 6161.46,137.04 6212.6,137.5 8905,140 6161.46,167.04 6212.6,167.5 2020,170 2815,190 2965,190 2735.85,190.87 2885.85,190.87 6161.46,197.04 6212.6,197.5 1981.5,235 1743.5,240 8905,260 2016,295 1725,295.75 1972,296 1690,360 4826.34,360 1345,393 7088.19,408.62 1971,444 2011,445 7640,445 1266,473 1808.5,515 2006.5,515 2820,545 2740.85,545.87 2890.85,545.87 3220,561.5 3290,561.5 3360,561.5 1700,575 1740,575 2060,575 2819.15,609.13 2969.15,609.13 2740,610 2890,610 1700,615 1740,615 2060,615 1322.13,747.57 4166,753 4265,753.62 2819.15,774.13 2969.15,774.13 2025,775 2740,775 2890,775 6432,777 2025,815 2820,835 2970,835 2740.85,835.87 2890.85,835.87 3375,870 3295.85,870.87 1986.5,880 1748.5,885 903,912.77 1790,940 2017,940 1730,940.75 1977,941 8175,950 1690,1010 3684.68,1036.61 3754.68,1036.61 3824.68,1036.61 8275,1050 1976,1090 2017,1090 8325,1100 5819.48,1118.95 5879.48,1118.95 1397.5,1133 3072.01,1135 1813.5,1160 2011.5,1160 6185.79,1162.53 6288.23,1171.81 5682.21,1179.8 5132,1182 2825,1190 2745.85,1190.87 2895.85,1190.87 1397.5,1213 1705,1220 1745,1220 2065,1220 5818.48,1221.15 5878.48,1221.15 3392.99,1230.75 8525,1250 5132,1252 2824.15,1254.13 2974.15,1254.13 2745,1255 2895,1255 1705,1260 1745,1260 2065,1260 3688.54,1271.5 3758.54,1271.5 3828.54,1271.5 5468.52,1295.79 5431.14,1327.79 5773.21,1327.79 8175,1350 4802,1382 4849,1382 5431.21,1416.79 5918,1418 5942,1418 5965,1418 2824.15,1439.13 2974.15,1439.13 2030,1440 2745,1440 2895,1440 2030,1480 5407.21,1482.79 2825,1500 2975,1500 8275,1500 8375,1500 2745.85,1500.87 2895.85,1500.87 4681.41,1517.62 4775.41,1517.62 5554.13,1528.79 3380,1535 3300.85,1535.87 1991.5,1545 1753.5,1550 4885,1567.5 5016,1571 4765,1595 8175,1600 1790.75,1605 1981,1605 2021,1605 1735,1605.75 5550.21,1641.16 5016,1665 4885,1667.5 1700,1670 5591.21,1672.79 5698.21,1672.79 5659.19,1676.79 4695,1700 8225,1700 8325,1700 8425,1700 8525,1700 3690,1701.93 3760,1701.93 3830,1701.93 4589.69,1705 5730.19,1712.79 8175,1750 8575,1750 8625,1750 1981,1754 2021,1754 3690,1790.43 3760,1790.43 3830,1790.43 3077.01,1800 8175,1800 8375,1800 8475,1800 8625,1800 5172.83,1805 1818.5,1825 2016.5,1825 8225,1850 8325,1850 8525,1850 2830,1855 2750.85,1855.87 2900.85,1855.87 1710,1885 1750,1885 2070,1885 4509.15,1884.71 3397.99,1895.75 8575,1900 2829.15,1919.13 2979.15,1919.13 2750,1920 2900,1920 6193.95,1921.72 6284.52,1921.72 1710,1925 1750,1925 2070,1925 4695,1925 7055.43,1931.41 7149.43,1931.41 6193.95,1951.72 6284.52,1951.72 4585,1970 4768.9,1970 4826.81,1970 6193.95,1981.72 6284.52,1981.72 6193.95,2011.72 6284.52,2011.72 4585,2020 7140.03,2019.51 7234.03,2019.51 4761.77,2027.09 6194.95,2041.72 6259.52,2041.72 1145,2060 6196.95,2071.72 6257.52,2071.72 2824.15,2089.13 2974.15,2089.13 2030,2090 2745,2090 2895,2090 8275,2100 8375,2100 8475,2100 6196.95,2101.72 6257.52,2101.72 1150,2105 2398,2119.75 2423,2119.75 2448,2119.75 2473,2119.75 2498,2119.75 2779.01,2123.02 2030,2130 6196.95,2131.72 6257.52,2131.72 2398,2144.75 2423,2144.75 2448,2144.75 2473,2144.75 2498,2144.75 2825,2150 2975,2150 8525,2150 2745.85,2150.87 2895.85,2150.87 6196.95,2161.72 6257.52,2161.72 2398,2169.75 2423,2169.75 2448,2169.75 3380,2185 3300.85,2185.87 1991.5,2195 6252.83,2195.78 1753.5,2200 8325,2200 8425,2200 8525,2200 7489.42,2211.46 6201.64,2215.41 3689.68,2217.67 3759.68,2217.67 3829.68,2217.67 6252.83,2233.78 6864.58,2234.32 1039.02,2245 6201.64,2253.41 1982,2255 1735,2255.75 2022,2256 6252.83,2271.78 1038.63,2281 3690.32,2283.39 3760.32,2283.39 3830.32,2283.39 1280,2290 1340,2290 1400,2290 1460,2290 6201.64,2291.41 7489.42,2305.46 2838,2306.95 2861,2306.95 6252.83,2309.78 1038.63,2319 6864.58,2328.32 6201.64,2329.41 1710,2340 1280,2345 1340,2345 1400,2345 1460,2345 6252.83,2347.78 2448,2354 7487.21,2360.38 6201.64,2367.41 2448,2379 1285,2395 1345,2395 1405,2395 1465,2395 1981,2404 2021,2404 2448,2404 7618.53,2408.53 7370,2411.02 7553.68,2426.84 7426.24,2432.94 3077.01,2450 1818.5,2475 2016.5,2475 7685,2475 7478.65,2485.35 7438.19,2500.1 6202,2503 2610.99,2504 6252.83,2503.78 2830,2505 2750.85,2505.87 2900.85,2505.87 3691.46,2508.5 3761.46,2508.5 3831.46,2508.5 1710,2535 1750,2535 2070,2535 3397.99,2545.75 6201.64,2547.5 6252.77,2547.96 6880,2553.62 6910,2559.69 2829.15,2569.13 2979.15,2569.13 2750,2570 2900,2570 7428,2574 1710,2575 1750,2575 2070,2575 6201.64,2577.5 6252.77,2577.96 7676,2583 7404.98,2604.67 7498.98,2604.67 6201.64,2607.5 6252.77,2607.96 7104,2613.57 6201.64,2637.5 6252.77,2637.96 7192.12,2645.83 7286.12,2645.83 7025,2664.69 6201.64,2667.5 6252.77,2667.96 7676,2677 6201.64,2697.5 6252.77,2697.96 7104,2707.57 6201.64,2727.5 6252.77,2727.96
  other v2: 8175,400 8325,400 8425,400 8525,400 8625,400 8725,400 8825,400 8225,450 8275,450 8375,450 8475,450 8575,450 8675,450 8775,450 8225,500 8325,500 8425,500 8525,500 8625,500 8675,500 8775,500 8175,550 8575,550 8725,550 8825,550 8175,600 8275,600 8375,600 8475,600 8625,600 8725,600 8825,600 8225,650 8325,650 8425,650 8525,650 8675,650 8775,650 8225,700 8675,700 8775,700 8175,750 8275,750 8375,750 8475,750 8625,750 8725,750 8825,750 8175,800 8325,800 8425,800 8525,800 8625,800 8725,800 8825,800 8225,850 8675,850 8775,850 8225,900 8275,900 8375,900 8475,900 8675,900 8775,900 8325,950 8425,950 8525,950 8625,950 8725,950 8825,950 8175,1000 8575,1000 8625,1000 8725,1000 8825,1000 8225,1050 8375,1050 8475,1050 8675,1050 8775,1050 8225,1100 8425,1100 8525,1100 8675,1100 8775,1100 8175,1150 8575,1150 8625,1150 8725,1150 8825,1150 8175,1200 8275,1200 8375,1200 8625,1200 8725,1200 8825,1200 8225,1250 8325,1250 8425,1250 8675,1250 8775,1250 8225,1300 8675,1300 8775,1300 8275,1350 8375,1350 8475,1350 8625,1350 8725,1350 8825,1350 8325,1400 8425,1400 8525,1400 8625,1400 8725,1400 8825,1400 8575,1450 8675,1450 8775,1450 8225,1500 8675,1500 8775,1500 8625,1550 8725,1550 8825,1550 8725,1600 8825,1600 8675,1650 8775,1650 8675,1700 8775,1700 8725,1750 8825,1750 8725,1800 8825,1800 8425,1850 8675,1850 8775,1850 8675,1900 8775,1900 8175,1950 8275,1950 8375,1950 8475,1950 8625,1950 8725,1950 8825,1950 8175,2000 8325,2000 8425,2000 8525,2000 8625,2000 8725,2000 8825,2000 8675,2050 8775,2050 8575,2100 8675,2100 8775,2100 8425,2150 8625,2150 8725,2150 8825,2150 8625,2200 8725,2200 8825,2200 8575,2250 8675,2250 8775,2250 8675,2300 8775,2300 8175,2350 8425,2350 8525,2350 8625,2350 8725,2350 8825,2350 2169.01,2459.52
  other v3: 7130.98,506.38 6188,1116 6286,1116 5868.2,1374.29 5810.89,1466.79 5776.21,1590.79 6198.15,1677.98 6275.71,1677.98 6254.39,1999.92
  other v4: 5187.25,382.13 5138.04,423.47 5187.25,423.47 5236.46,423.47 5187.25,464.81 755.27,694.17 801.45,694.17 847.63,694.17 668.03,735.23 709.09,735.23 755.27,735.23 801.45,735.23 847.63,735.23 709.09,781.41 801.45,781.41 847.63,781.41 888.7,781.41 709.09,827.59 755.27,827.59 847.63,827.59 709.09,873.77 755.27,873.77 801.45,873.77 847.63,873.77 888.7,873.77 709.09,914.83 801.45,914.83 847.63,914.83 3211.49,1143 3272.51,1143 5594.29,1354.64 5651.77,1354.64 5544.29,1404.64 5594.29,1404.64 5651.77,1404.64 5701.77,1404.64 5544.29,1462.12 5594.29,1512.12 5651.77,1512.12 3216.49,1808 3277.51,1808 4715.12,1811.57 4766.3,1811.57 4817.48,1811.57 4766.3,1862.76 1167.56,2152.6 1144.92,2190 1190.2,2190 1167.56,2227.4 7080,2266.94 7133.54,2266.94 7187.09,2266.94 7240.63,2266.94 7028.43,2318.51 7080,2318.51 7133.54,2318.51 7187.09,2318.51 7240.63,2318.51 7292.2,2318.51 7028.43,2372.05 7080,2372.05 7133.54,2372.05 7187.09,2372.05 7240.63,2372.05 7292.2,2372.05 7028.43,2425.6 7080,2425.6 7133.54,2425.6 7187.09,2425.6 7240.63,2425.6 7292.2,2425.6 3216.49,2458 3277.51,2458 7028.43,2479.14 7080,2479.14 7133.54,2479.14 7187.09,2479.14 7240.63,2479.14 7292.2,2479.14 7080,2530.71 7133.54,2530.71 7187.09,2530.71 7240.63,2530.71
  other v5: 6120,1580 6080,1600 6160,1600 6315,1600 6040,1620 6120,1620 6080,1640 6160,1640 6315,1640 6040,1660 6120,1660 6080,1680 6160,1680 6315,1680 6040,1700 6120,1700 6160,1720 6315,1720 6120,1740 6330.81,1750.81 6160,1760 6360,1760 6120,1780 6320,1780 6360,1800 6320,1820 6126,1822 6147,1822 6120,1900 6065,1913 6086,1913 6318.16,1980 6358.16,1980 6398.16,1980 6438.16,1980 6098.16,2020 6318.16,2020 6358.16,2020 6398.16,2020 6438.16,2020 6098.16,2060 6138.16,2060 6318.16,2060 6358.16,2060 6398.16,2060 6438.16,2060 6098.16,2100 6138.16,2100 6318.16,2100 6358.16,2100 6398.16,2100 6438.16,2100 6058.16,2140 6098.16,2140 6138.16,2140 6318.16,2140 6358.16,2140 6398.16,2140 6438.16,2140 6018.16,2180 6058.16,2180 6098.16,2180 6138.16,2180 6178.16,2180 6278.16,2180 6318.16,2180 6358.16,2180 6398.16,2180 6438.16,2180 6018.16,2220 6058.16,2220 6098.16,2220 6138.16,2220 6318.16,2220 6358.16,2220 6398.16,2220 6438.16,2220 6058.16,2260 6098.16,2260 6138.16,2260 6178.16,2260 6278.16,2260 6318.16,2260 6358.16,2260 6398.16,2260 6438.16,2260 6398.16,2300 6438.16,2300 6398.16,2340 6438.16,2340
  other v6: 6227.17,234.38 6148.45,234.93 6226.72,271.45 6148,272 6242,327.54 6257,345.54 6307,345.54 6342,345.54 6242,357.54 5878.33,641.74 6593.59,642.65 6633.56,644.32 5838.49,645.37 5905.82,670.8 6567.49,672.95 6657.23,676.56 5816.35,678.68 5930.71,702.11 6541.79,703.61 6646.85,715.19 5828.47,716.8 5958.99,730.4 6513.51,731.9 6612.65,735.94 5862.77,737.37 5987.27,758.68 6485.23,760.18 6584.37,764.23 5891.06,765.65 6015.56,786.96 6456.94,788.46 6556.08,792.51 5919.34,793.94 6043.84,815.25 6428.66,816.75 6527.8,820.79 5947.63,822.22 6072.13,843.53 6400.37,845.03 6499.52,849.08 5975.91,850.51 6101.95,870.18 6370.4,871.52 6181.05,877.14 6471.23,877.36 6291.24,877.9 6004.2,878.79 6141.07,878.54 6331.21,879.52 6442.95,905.65 6032.48,907.07 6412.08,931.09 6063.85,931.89 6100.86,947.07 6375.49,947.25 6184.52,948.94 6140.61,951.51 6335.83,952.48 6295.85,953.5 6184.52,988.94 6289.48,998.22 6184.52,1028.94 6289.48,1038.22 6182.47,1068.89 6291.53,1078.17 6348,1912.99
  other v7: 6126.77,1201.77 6158.27,1201.77 6189.76,1201.77 6284.25,1201.77 6315.75,1201.77 6473.23,1201.77 6158.27,1233.27 6189.76,1233.27 6221.26,1233.27 6252.76,1233.27 6284.25,1233.27 6315.75,1233.27 6473.23,1233.27 6126.77,1296.26 6284.25,1296.26 6378.74,1296.26 6410.24,1296.26 6126.77,1327.76 6284.25,1327.76 6158.27,1359.25 6189.76,1359.25 6284.25,1359.25 6378.74,1359.25 6410.24,1359.25 6158.27,1390.75 6189.76,1390.75 6284.25,1390.75 6378.74,1390.75 6410.24,1390.75 6126.77,1422.24 6284.25,1422.24 6126.77,1453.74 6284.25,1453.74 6378.74,1453.74 6410.24,1453.74 6284.25,1485.24 6158.27,1516.73 6315.75,1516.73 6473.23,1516.73 6126.77,1548.23 6158.27,1548.23 6284.64,1548.23 6315.75,1548.23 6473.23,1548.23
  other v8: 6152,327.54 6222,327.54 6156.7,345.04 6217.3,345.04 6169.5,357.84 6204.5,357.84 6187,362.54 6192,772.54 6282,772.54 6174.5,777.24 6209.5,777.24 6264.5,777.24 6299.5,777.24 6161.7,790.04 6223.3,790.04 6249.7,790.04 6312.3,790.04 6157,807.54 6227,807.54 6247,807.54 6317,807.54
  other v10: 6177,482.34 6237,482.34 6297,482.34 6177,562.34 6237,562.34 6297,562.34 6177,629.34 6237,629.34 6297,629.34 6172,749.04 6237,749.04 6302,749.04
  other v12: 53,587 78,587 103,587 128,587 270,587 295,587 320,587 345,587 53,992 78,992 103,992 128,992 269,992 294,992 319,992 344,992
  other v13: 5522.84,1881.14 5593.71,1881.14 5478,1916.95 5644.89,1916.57 5471.66,2026.81 5644.89,2026.81 5522.84,2062.24 5593.71,2062.24 5786,2167.92 5896.23,2167.92 5750.57,2219.1 5931.67,2219.1 5750.56,2289.96 5931.67,2289.96 5786,2341.15 5896.23,2341.15
  other v19: 5999.5,110 6374.5,110 6039.73,2635 6414.73,2635
GND2: J5.2 J5.3 J5.4 J5.5 J22.2 J22.3 J22.4 J22.5 J27.2 J27.3 J27.4 J27.5 J28.2 J28.3 J28.4 J28.5 J29.2 J29.3 J29.4 J29.5 J30.2 J30.3 J30.4 J30.5 J31.2 J31.3 J31.4 J31.5 J32.2 J32.3 J32.4 J32.5 J33.2 J33.3 J33.4 J33.5 T3.1 T3.4 T4.4 T5.4 T6.4 T7.1 T7.4 | length 351
  Top Copper w18: T7.1@9656.5,440 9660.53,444.03 9683.51,444.03 9719,479.52 v15(9719,490) 9719,495 9764,540 T7.4@9781.5,540 ; T3.4@9862.5,1088.48 9880,1088.48 9925,1133.48 v15(9925,1138.48) 9925,1148.97 9960.49,1184.45 9983.47,1184.45 T3.1@9987.5,1188.48
  other v1: 9405.29,219.24 9367.75,225.13 9435,242.94 9346.6,256.7 9454.09,275.8 9355.45,293.66 9480.96,302.67 9840.74,303.53 9388.66,312.12 9877.36,313.67 9805.38,317.45 9507.83,329.54 9416.23,338.27 9901.69,342.86 9783.39,348.44 9521.8,353.6 9559.24,360.08 9597.24,360.08 9635.24,360.08 9673.24,360.08 9711.24,360.08 9443.1,365.14 9747.03,372.86 9904.47,380.76 9782.53,386.43 9468.94,393 10296.01,394.11 9939.35,395.84 10003.93,395.59 10041.93,395.59 10079.51,401.19 10333.46,400.53 10145.5,403 10183.46,404.53 10221.46,404.53 10259.46,404.53 10107.73,407.22 9487.91,412.14 9512.88,417.13 9555.42,431.03 9593.42,431.03 10354.15,432.41 9707.34,433.51 9517.71,435.71 9492.49,466.37 10344.78,469.23 10189.4,475.47 10227.4,475.47 10265.4,475.47 9832.93,476.17 10113.4,475.5 10151.4,475.57 9993.49,483.43 9757.83,484.41 9795.83,484.41 10031.48,484.41 10063.95,484.16 10311.28,487.17 9476.48,500.83 9847.29,514.61 9547.42,526.71 9584.38,535.55 9476.48,538.83 9823.86,544.53 9558.6,563.03 9600,570.19 9959.5,574.6 9483.36,576.2 9635.24,584.41 9922.79,584.41 9672.95,589.12 9886.05,594.12 9458.45,599.5 9559.21,601.02 9702.43,613.09 9740.36,615.47 9778.36,615.47 9816.36,615.47 9854.36,615.08 9431.58,626.37 9530.14,625.5 9404.71,653.24 9501.58,656.72 9372,672.59 9474.71,683.59 9347.66,701.76 9447.84,710.46 9352.63,739.43 9430.42,744.23 9396.92,762.17 10238.16,867.84 10275.76,873.29 10208.76,891.92 10297.28,904.61 10189.51,924.68 10288.87,941.66 10162.64,951.55 10255.91,960.57 10135.77,978.42 10228.08,986.44 9832.7,1008.01 9870.7,1008.01 9908.7,1008.01 9946.7,1008.01 9984.7,1008.01 10022.7,1008.01 10060.7,1008.01 10098.7,1008.01 9794.71,1008.66 10201.21,1013.31 9763.29,1030.03 9727.98,1044.07 10171,1047.91 9690.33,1049.19 10146.97,1070.45 10073.48,1078.96 10111.22,1083.36 9808.17,1085.48 10048.6,1107.68 9793.04,1120.33 9350.11,1143.13 9607.35,1144.07 9645.35,1144.32 9834.25,1144.07 9872.25,1144.07 9569.45,1146.84 9312.4,1147.77 9500.76,1151.19 9386.81,1153.01 9424.81,1153.01 9462.81,1153.01 9538.28,1157.25 9802.59,1165.09 9290.29,1178.68 10119.74,1192.06 10044.21,1198.01 10082.21,1198.01 9298,1215.89 9376.47,1223.96 9414.47,1223.96 9452.47,1223.96 9490.47,1223.96 10164.32,1223.88 9528.45,1224.88 9574.82,1231.96 9612.81,1232.9 9644.95,1232.64 9714.72,1232.9 9340.31,1235.65 9752.57,1236.22 10189.71,1252.15 9780.03,1262.49 9817.48,1268.96 9855.48,1268.96 9893.48,1268.96 9931.48,1268.96 9969.48,1268.96 10007.48,1268.96 10045.48,1268.96 10083.48,1268.96 10110.16,1275.83 10216.58,1279.02 10138.44,1301.22 10243.45,1305.89 10276.85,1324.01 10165.31,1328.09 10192.18,1354.96 10297.54,1355.89 10210.57,1388.21 10288.17,1392.72 10254.67,1410.65 9709.8,1463.4 9747.63,1467 9682.68,1490.02 9769.33,1498.2 9685.6,1527.9 9760.47,1535.15 9689.53,1565.7 9760.47,1573.15 9689.53,1603.7 9760.47,1611.15 9689.53,1641.7 9760.47,1649.15 9687.48,1679.65 9762.52,1687.1 9686.48,1717.65 9761.52,1725.1 9910.37,2300.53 9603.21,2302.31 9948.31,2302.66 9763.94,2309.86 9786.02,2309.62 9568.15,2316.96 9983.13,2317.88 9540.15,2342.65 9747.95,2344.33 9801.9,2344.14 10010.96,2343.76 9716.97,2366.34 9832.81,2366.24 9511.87,2368.04 10039.24,2369.15 9641.32,2371.47 9679.32,2371.47 9870.45,2371.47 9908.45,2371.47 9604.08,2379.05 9945.72,2378.86 10058.93,2388.84 9486.87,2394.23 9578.2,2406.88 9971.64,2406.66 10084.32,2417.12 9460.86,2421.94 9989.76,2424.7 9549.13,2431.35 10111.19,2443.99 9433.99,2448.81 10017.52,2450.65 10138.06,2470.86 9510.34,2472.79 9407.12,2475.68 10044.39,2477.52 10169.51,2492.19 9374.81,2495.68 9483.47,2499.66 10071.26,2504.39 10193.61,2521.57 9456.6,2526.53 9355.19,2528.22 10098.13,2531.26 9436.76,2558.94 10186.76,2558.94 9367.36,2564.22 10117.23,2564.11 9403.79,2577.84 10153.79,2577.84
  other v6: 9780,1779.48 9795,1797.48 9845,1797.48 9880,1797.48 9780,1809.48
  other v8: 9690,1779.48 9760,1779.48 9694.7,1796.98 9755.3,1796.98 9707.5,1809.78 9742.5,1809.78 9725,1814.48 9730,2224.48 9820,2224.48 9712.5,2229.18 9747.5,2229.18 9802.5,2229.18 9837.5,2229.18 9699.7,2241.98 9850.3,2241.98 9695,2259.48 9765,2259.48 9785,2259.48 9855,2259.48
  other v10: 9715,1934.28 9775,1934.28 9835,1934.28 9715,2014.28 9775,2014.28 9835,2014.28 9715,2081.28 9775,2081.28 9835,2081.28 9710,2200.98 9775,2200.98 9840,2200.98 9761.3,2241.98 9788.7,2241.98
  other v15: 9969,440 9969,490 9969,540 10014.5,575 10048.5,575 9595.5,1053.48 9629.5,1053.48 9675,1088.48 9675,1138.48 9675,1188.48
HSPC-PRSNT-M2C-L: J1.Z1 R107.1
  other v2: 8775,2350
INA_ADC_N: R183.2 U1.A5 | length 44.8
  Top Copper w10.5: R183.2@6248.92,1592.01 6248.92,1557.49 ccw(c6262.02,1557.49) U1.A5@6252.76,1548.23
INA_ADC_P: R188.2 U1.A4 | length 44.8
  Top Copper w11.5: U1.A4@6221.26,1548.23 ccw(c6212.43,1557.06) 6224.92,1557.06 R188.2@6224.92,1592.01
INB_ADC_N: R15.2 U1.M5 | length 43.6
  Top Copper w9: U1.M5@6252.76,1201.77 U1.M5@6253,1201.53
  Top Copper w10.5: U1.M5@6252.26,1201.53 U1.M5@6252.5,1201.77
  Top Copper w11.5: U1.M5@6252.76,1201.77 6252.76,1159.24 R15.2@6253,1158.99
INB_ADC_P: R11.2 U1.M4 | length 43.3
  Top Copper w9: U1.M4@6221,1201.51 U1.M4@6221.26,1201.77
  Top Copper w11.5: R11.2@6221,1158.99 6221.26,1159.25 U1.M4@6221.26,1201.77
INB_SMA: C75.2 J7.1 | length 226.6
  Top Copper w11.5: J7.1@6187,17.5 C75.2@6187,244.06
INB_SMA_N: C93.2 J8.1 | length 424.4
  Top Copper w11.5: C93.2@6278.96,916 6339.58,916 cw(c6339.58,816) 6410.29,886.71 J8.1@6612,685
INB_SMA_P: C74.2 J6.1 | length 424
  Top Copper w11.5: J6.1@5862,685 6062.73,885.73 cw(c6133.44,815.02) 6133.44,915.02 C74.2@6195.02,915.02
LMK_REF_N: C50.2 C508.1 R451.1 | length 2784.9
  Layer 3 (SIG1) w3.25: v1(4713.41,1517.62) ccw(c4695.6,1535.43) 4720.78,1535.43 4720.78,1548.66 cw(c4745.37,1548.66) 4745.37,1573.25 4769.46,1573.25 cw(c4769.46,1490.46) 4828,1549 ccw(c4893.18,1614.18) 4893.18,1522 5011.58,1522 ccw(c5011.58,1622) 5082.29,1551.29 5250,1719 ccw(c5179.99,1789.01) 5279,1789.01 5279,1861.92 cw(c5353.26,1861.92) 5300.75,1914.43 5755.99,2369.67 cw(c5834.65,2291) 5834.65,2402.25 6627.58,2402.25 cw(c6627.58,2291) 6706.24,2369.67 6713.18,2362.73 ; v1(6864.58,2296.32) 6856.87,2288.6 cw(c6853,2292.47) 6853,2287 6830.33,2287 cw(c6830.33,2387) 6759.62,2316.29 6713.24,2362.67 ; 6713.18,2362.73 cw(c6634.58,2284) 6713.24,2362.67 ; 6713.18,2362.73 6713.24,2362.67
  Bottom Copper w10.5: v1(4713.41,1517.62) cw(c4716.81,1521.03) 4712,1521.03 4712,1551.73 cw(c4722.24,1551.73) C508.1@4715,1558.98 ; v1(6864.58,2296.32) ccw(c6866.55,2298.29) 6866.55,2295.5 6883.97,2295.5 cw(c6883.97,2280.22) 6894.78,2291.02 R451.1@6900,2291.02 6909.97,2291.02 ccw(c6909.97,2294.83) 6912.66,2292.14 cw(c6913.53,2292.14) 6913.53,2293 C50.2@6925,2293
